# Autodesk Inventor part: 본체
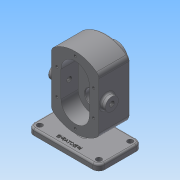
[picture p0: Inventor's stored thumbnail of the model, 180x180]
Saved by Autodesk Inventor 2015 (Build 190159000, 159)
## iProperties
Created: 2019-03
Part Number: 본체
Material: 일반
Document SubType Name: Modeling
Designer: user
Density: 1 g/cm^3
Appearance: 기본값
Author: user
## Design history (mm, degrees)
sketch "스케치2"
  geometry: L1 (-60, -36.5)-(60, -36.5); L2 (60, -36.5)-(60, 36.5); L3 (60, 36.5)-(-60, 36.5); L4 (-60, 36.5)-(-60, -36.5); L5 (-60, -36.5)-(60, 36.5); L6 (60, -36.5)-(-60, 36.5); 1 further point
  constraints: 12 end point, 2 midpoint, 2 parallel, 1 horizontal, 1 perpendicular
  dimensions: "d0" = 120 distance of L3.end L2.end; "d1" = 73 distance of L2.end L1.end
extrude "돌출1" new body sketch "스케치2" distance "d2" = 10; taper "d3" = 0 deg
fillet "모깎기1" dims "d4" = 10
sketch "스케치3"
  geometry: A1 r 10 centre (-50, -26.5) between (-60, -26.5) and (-50, -36.5) reference; A2 r 10 centre (50, -26.5) between (50, -36.5) and (60, -26.5) reference; A3 r 10 centre (50, 26.5) between (60, 26.5) and (50, 36.5) reference; A4 r 10 centre (-50, 26.5) between (-50, 36.5) and (-60, 26.5) reference; 1 further point
hole "구멍1" sketch "스케치3" at (50, -26.5), (50, 26.5), (-50, 26.5), (-50, -26.5) diameter "d5" = 9; stored, may be unused: countersink angle "d9" = 90 deg, drill point angle "d11" = 0 deg; dims "d6" = 6, "d7" = 4, "d8" = 2, "d10" = 8
node "작업 평면1"
sketch "스케치4"
  geometry: L1 (-100, -10)-(0, -10) reference; L2 (-90, 68)-(-10, 68); L3 (-90, 68)-(-90, 112.721); L4 (-10, 68)-(-10, 112.721); L5 (-90, 68)-(-90, 23.279); L6 (-10, 68)-(-10, 23.279); A1 r 60 centre (-50, 68) between (-10, 112.721) and (-90, 112.721); A2 r 60 centre (-50, 68) between (-90, 23.279) and (-10, 23.279); 2 further points
  constraints: 10 end point, 4 point on circle, 2 centre point, 2 symmetric about line, 2 vertical, 1 coincident, 1 horizontal, 1 midpoint, 1 vertical alignment, 1 other
  dimensions: "d22" = 80 distance of L2.start L2.end; "d23" = 78 distance between parallel lines of L1 L2; "d24" = 60 radius of A1; "d25" = 138 dimension on A1 L1 (derived)
extrude "돌출2" join sketch "스케치4" distance "d26" = 53; taper "d27" = 0 deg
sketch "스케치6"
  geometry: L1 (-50, 90)-(-50, 46); L2 (-74, 90)-(-74, 46); L3 (-26, 46)-(-26, 90); A1 r 60 centre (-50, 68) between (-90, 23.279) and (-10, 23.279) reference; A2 r 24 centre (-50, 90) between (-26, 90) and (-74, 90); A3 r 24 centre (-50, 46) between (-74, 46) and (-26, 46); 2 further points
  constraints: 8 end point, 4 point on circle, 4 tangent, 2 centre point, 1 coincident, 1 midpoint, 1 parallel, 1 vertical
  dimensions: "d28" = 48 diameter of A3; "d29" = 44 distance of L1.start L1.end
extrude "돌출3" cut sketch "스케치6" distance "d30" = 29; taper "d31" = 0 deg
sketch "스케치7"
  geometry: C1 r 12.5 at (-50, 46); C2 r 12.5 at (-50, 90); A1 r 24 centre (-50, 46) between (-74, 46) and (-26, 46) reference; A2 r 24 centre (-50, 90) between (-26, 90) and (-74, 90) reference; 1 further point
  constraints: 2 centre point, 2 coincident
  dimensions: "d32" = 25 diameter of C1; "d33" = 25 diameter of C2
extrude "돌출4" cut sketch "스케치7" distance "d34" = 15; taper "d35" = 0 deg
sketch "스케치14"
  geometry: C1 r 12.5 at (50, 90) reference; C2 r 19 at (50, 90); 1 further point
  constraints: 1 centre point, 1 coincident
  dimensions: "d53" = 38 diameter of C2
extrude "돌출8" join sketch "스케치14" distance "d54" = 17; taper "d55" = 0 deg
sketch "스케치15"
  geometry: C1 r 12.5 at (0, 0) reference; C2 r 8.5 at (0, 0); 1 further point
  constraints: 1 centre point, 1 coincident
  dimensions: "d56" = 17 diameter of C2
extrude "돌출9" cut sketch "스케치15" stored distance "d57" = 17; taper "d58" = 0 deg
sketch "스케치16"
  geometry: C1 r 19 at (0, 0) reference; C2 r 14 at (0, 0); 1 further point
  constraints: 1 centre point, 1 coincident
  dimensions: "d60" = 28 diameter of C2
extrude "돌출10" cut sketch "스케치16" distance "d61" = 7.3; taper "d62" = 0 deg
fillet "모깎기4" dims "d63" = 0.5
sketch "스케치18"
  geometry: L1 (50, 36.5)-(-50, 36.5) reference; L2 (-6, 36.5)-(6, 36.5); L3 (6, 36.5)-(6, -6.5); L4 (6, -6.5)-(-6, -6.5); L5 (-6, -6.5)-(-6, 36.5); 2 further points
  constraints: 8 end point, 1 collinear, 1 horizontal, 1 midpoint, 1 perpendicular, 1 vertical, 1 vertical alignment
  dimensions: "d68" = 12 distance of L2.start L2.end; "d69" = 43 distance of L2.end L3.end; "d70" = 12 distance of L3.end L4.end
extrude "돌출11" join sketch "스케치18" stored distance "d71" = 43; taper "d72" = 0 deg
sketch "스케치19"
  geometry: L1 (-50, 90)-(-50, 46); L2 (-81, 90)-(-81, 46); L3 (-19, 46)-(-19, 90); A1 r 24 centre (-50, 46) between (-74, 46) and (-26, 46) reference; A2 r 24 centre (-50, 90) between (-26, 90) and (-74, 90) reference; A3 r 60 centre (-50, 68) between (-10, 112.721) and (-90, 112.721) reference; A4 r 31 centre (-50, 90) between (-19, 90) and (-81, 90); A5 r 31 centre (-50, 46) between (-81, 46) and (-19, 46); 8 further points
  constraints: 10 point on circle, 8 end point, 4 tangent, 2 centre point, 2 horizontal alignment, 1 midpoint, 1 parallel, 1 vertical, 1 vertical alignment
  dimensions: "d73" = 62 diameter of A5; "d74" = 22 vertical distance of point (-19, 90) A3.centre; "d75" = 44 distance of point (-19, 46) point (-19, 90)
hole "구멍2" sketch "스케치19" at (-50, 121), (-50, 15), (-19, 90), (-19, 46), (-81, 90), (-81, 46) diameter "d76" = 4.134; stored, may be unused: countersink angle "d80" = 90 deg, drill point angle "d82" = 118 deg; dims "d77" = 10, "d78" = 4, "d79" = 2, "d81" = 12
fillet "모깎기5" dims "d83" = 10
sketch "스케치20"
  geometry: L1 (0, 0)-(0, 80) reference; L2 (43, -38)-(-10, -38) reference; C1 r 11 at (14, 40); 1 further point
  constraints: 1 centre point
  dimensions: "d84" = 22 diameter of C1; "d85" = 14 distance from line of C1.centre L1; "d86" = 78 distance from line of L2 C1.centre
extrude "돌출12" join sketch "스케치20" distance "d87" = 8; taper "d88" = 0 deg
sketch "스케치21"
  geometry: C1 r 11 at (0, 0) reference; 1 further point
hole "구멍3" sketch "스케치21" at (0, 0) diameter "d89" = 8.376; stored, may be unused: countersink angle "d93" = 90 deg, drill point angle "d95" = 118 deg; dims "d90" = 20, "d91" = 4, "d92" = 2, "d94" = 27.3
sketch "스케치22"
  geometry: C1 r 11 at (0, 0) reference; 1 further point
hole "구멍4" sketch "스케치22" at (0, 0) diameter "d96" = 8.376; stored, may be unused: countersink angle "d100" = 90 deg, drill point angle "d102" = 118 deg; dims "d97" = 20, "d98" = 4, "d99" = 2, "d101" = 27.3
fillet "모깎기6" dims "d103" = 3
fillet "모깎기7" dims "d104" = 3
fillet "모깎기8" dims "d105" = 3
fillet "모깎기9" dims "d106" = 3
fillet "모깎기10" dims "d107" = 3
sketch "스케치23"
  geometry: L1 (-20.739, -23.498)-(20.739, -23.498); L2 (20.739, -23.498)-(20.739, -29.502); L3 (20.739, -29.502)-(-20.739, -29.502); L4 (-20.739, -29.502)-(-20.739, -23.498); L5 (-20.739, -26.5)-(20.739, -26.5); L6 (0, -29.502)-(0, -23.498); L7 (-60, 26.5)-(-60, -26.5) reference; L8 (-50, -36.5)-(50, -36.5) reference; 1 further point
  constraints: 4 end point, 4 midpoint, 2 other
  dimensions: "d108" = 60 distance between parallel lines of L6 L7; "d109" = 10 distance between parallel lines of L5 L8
feature "엠보싱1" sketch "스케치23" dims "d0" = 120, "d1" = 73, "d110" = 0.5, "d111" = 0
sketch "스케치24"
  geometry: 1 further point
chamfer "모따기4" distance "d112" = 1; stored, may be unused: second distance "d113" = 2, angle "d114" = 45 deg
chamfer "모따기5" distance "d116" = 0.7; stored, may be unused: second distance "d117" = 2, angle "d118" = 15 deg
node "솔리드1"
mirror "대칭1"
node "투영된 루프2"
other parameters: "d12" = -53
